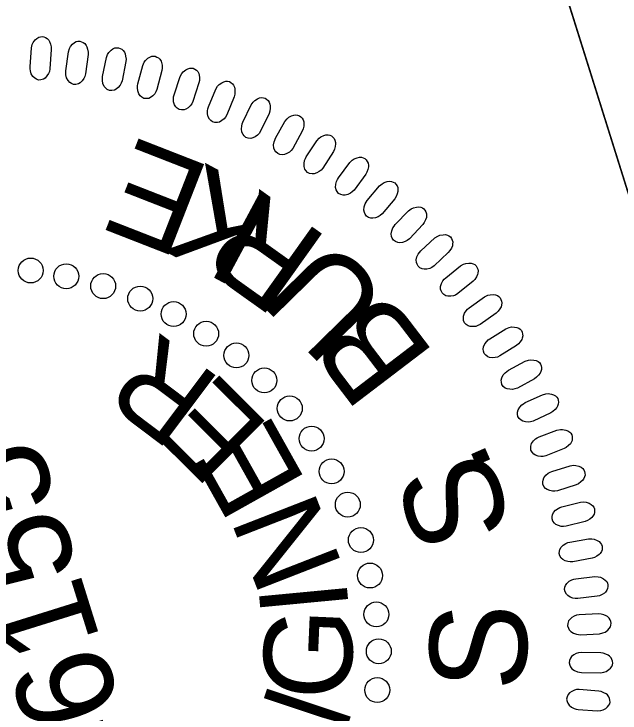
# Model space of a CAD drawing. Extents: x 473667 to 478950, y 494687 to 505998.
# Drawn here: x 473807.69 to 473846.62, y 505639.65 to 505684.57 of the extents above; entities that cross this region are included whole.
import ezdxf

# ---------------------------------------------------------------- set-up
doc = ezdxf.new("R2010")
doc.units = 0
for name, color, linetype in [('Sheet PE Seal Cell', 7, 'Continuous'), ('Sheet Plan CELL', 7, 'Continuous'), ('Sheet Sticker Exception Certification CELL', 7, 'Continuous'), ('Sheet Sticker Incomplete CELL', 7, 'Continuous')]:
    doc.layers.add(name, color=color, linetype=linetype)

msp = doc.modelspace()

# ---------------------------------------------------------------- linework, layer by layer
at = {"layer": 'Sheet PE Seal Cell'}
for points in [[(473808.719, 505681.168), (473808.81, 505682.391), (473808.863, 505682.607), (473808.925, 505682.743), (473809.05, 505682.904), (473809.155, 505683.006), (473809.273, 505683.077), (473809.38, 505683.109), (473809.494, 505683.121), (473809.604, 505683.093), (473809.721, 505683.054), (473809.821, 505682.987), (473809.918, 505682.879), (473809.972, 505682.795), (473810.028, 505682.641), (473810.074, 505682.458), (473810.085, 505682.297), (473809.999, 505681.043), (473809.965, 505680.876), (473809.91, 505680.74), (473809.808, 505680.588), (473809.687, 505680.456), (473809.584, 505680.384), (473809.422, 505680.336), (473809.272, 505680.327), (473809.126, 505680.378), (473809.025, 505680.436), (473808.906, 505680.544), (473808.799, 505680.722), (473808.745, 505680.907), (473808.725, 505681.038)], [(473811.016, 505680.921), (473811.183, 505682.136), (473811.25, 505682.348), (473811.32, 505682.48), (473811.455, 505682.632), (473811.566, 505682.728), (473811.688, 505682.792), (473811.797, 505682.817), (473811.911, 505682.821), (473812.019, 505682.786), (473812.133, 505682.74), (473812.229, 505682.667), (473812.319, 505682.554), (473812.368, 505682.467), (473812.414, 505682.309), (473812.448, 505682.123), (473812.449, 505681.962), (473812.285, 505680.716), (473812.24, 505680.551), (473812.176, 505680.419), (473812.066, 505680.273), (473811.936, 505680.151), (473811.829, 505680.085), (473811.665, 505680.047), (473811.514, 505680.047), (473811.372, 505680.107), (473811.275, 505680.171), (473811.162, 505680.287), (473811.067, 505680.471), (473811.025, 505680.658), (473811.013, 505680.79)], [(473813.379, 505680.562), (473813.622, 505681.765), (473813.702, 505681.972), (473813.781, 505682.099), (473813.924, 505682.243), (473814.042, 505682.331), (473814.167, 505682.387), (473814.278, 505682.406), (473814.391, 505682.403), (473814.498, 505682.361), (473814.609, 505682.308), (473814.699, 505682.229), (473814.782, 505682.11), (473814.825, 505682.02), (473814.861, 505681.86), (473814.884, 505681.672), (473814.875, 505681.512), (473814.634, 505680.278), (473814.578, 505680.117), (473814.506, 505679.988), (473814.387, 505679.85), (473814.249, 505679.735), (473814.138, 505679.677), (473813.973, 505679.649), (473813.821, 505679.659), (473813.683, 505679.728), (473813.591, 505679.798), (473813.485, 505679.92), (473813.402, 505680.109), (473813.372, 505680.3), (473813.368, 505680.432)], [(473815.639, 505680.079), (473815.956, 505681.264), (473816.05, 505681.466), (473816.136, 505681.587), (473816.288, 505681.722), (473816.411, 505681.803), (473816.54, 505681.851), (473816.651, 505681.862), (473816.765, 505681.852), (473816.867, 505681.804), (473816.976, 505681.744), (473817.061, 505681.659), (473817.136, 505681.536), (473817.174, 505681.443), (473817.199, 505681.281), (473817.211, 505681.092), (473817.192, 505680.932), (473816.872, 505679.716), (473816.807, 505679.559), (473816.727, 505679.436), (473816.6, 505679.305), (473816.455, 505679.199), (473816.341, 505679.147), (473816.173, 505679.13), (473816.023, 505679.15), (473815.89, 505679.227), (473815.802, 505679.302), (473815.704, 505679.431), (473815.633, 505679.626), (473815.614, 505679.817), (473815.619, 505679.95)], [(473817.969, 505679.383), (473818.361, 505680.545), (473818.466, 505680.741), (473818.56, 505680.857), (473818.721, 505680.982), (473818.848, 505681.055), (473818.98, 505681.095), (473819.091, 505681.099), (473819.204, 505681.082), (473819.304, 505681.027), (473819.408, 505680.961), (473819.488, 505680.871), (473819.554, 505680.743), (473819.586, 505680.648), (473819.602, 505680.485), (473819.602, 505680.295), (473819.572, 505680.137), (473819.178, 505678.944), (473819.102, 505678.791), (473819.015, 505678.673), (473818.88, 505678.55), (473818.729, 505678.453), (473818.611, 505678.409), (473818.443, 505678.402), (473818.295, 505678.432), (473818.166, 505678.517), (473818.083, 505678.597), (473817.994, 505678.732), (473817.935, 505678.931), (473817.929, 505679.123), (473817.942, 505679.255)], [(473820.184, 505678.605), (473820.648, 505679.74), (473820.765, 505679.929), (473820.865, 505680.039), (473821.034, 505680.154), (473821.166, 505680.218), (473821.3, 505680.25), (473821.411, 505680.247), (473821.523, 505680.222), (473821.618, 505680.162), (473821.718, 505680.089), (473821.792, 505679.994), (473821.852, 505679.862), (473821.877, 505679.765), (473821.882, 505679.602), (473821.87, 505679.413), (473821.83, 505679.257), (473821.362, 505678.09), (473821.277, 505677.942), (473821.182, 505677.83), (473821.04, 505677.716), (473820.883, 505677.629), (473820.762, 505677.592), (473820.594, 505677.596), (473820.449, 505677.635), (473820.326, 505677.728), (473820.248, 505677.814), (473820.168, 505677.954), (473820.121, 505678.156), (473820.126, 505678.348), (473820.148, 505678.479)], [(473822.388, 505677.625), (473822.923, 505678.729), (473823.052, 505678.91), (473823.16, 505679.013), (473823.335, 505679.117), (473823.47, 505679.173), (473823.606, 505679.196), (473823.717, 505679.186), (473823.827, 505679.155), (473823.919, 505679.089), (473824.013, 505679.009), (473824.082, 505678.911), (473824.132, 505678.775), (473824.152, 505678.677), (473824.147, 505678.513), (473824.123, 505678.325), (473824.073, 505678.172), (473823.533, 505677.038), (473823.439, 505676.895), (473823.337, 505676.789), (473823.187, 505676.684), (473823.026, 505676.607), (473822.903, 505676.578), (473822.736, 505676.592), (473822.592, 505676.64), (473822.475, 505676.741), (473822.403, 505676.832), (473822.332, 505676.976), (473822.299, 505677.181), (473822.316, 505677.372), (473822.345, 505677.502)], [(473824.486, 505676.593), (473825.089, 505677.661), (473825.23, 505677.834), (473825.344, 505677.93), (473825.525, 505678.023), (473825.663, 505678.071), (473825.8, 505678.085), (473825.911, 505678.068), (473826.019, 505678.03), (473826.106, 505677.958), (473826.196, 505677.873), (473826.258, 505677.77), (473826.3, 505677.631), (473826.313, 505677.532), (473826.298, 505677.369), (473826.262, 505677.183), (473826.203, 505677.033), (473825.592, 505675.935), (473825.489, 505675.798), (473825.381, 505675.699), (473825.225, 505675.604), (473825.059, 505675.537), (473824.935, 505675.516), (473824.769, 505675.54), (473824.629, 505675.597), (473824.518, 505675.705), (473824.452, 505675.8), (473824.39, 505675.949), (473824.369, 505676.155), (473824.398, 505676.345), (473824.436, 505676.472)], [(473826.464, 505675.396), (473827.133, 505676.425), (473827.283, 505676.589), (473827.403, 505676.677), (473827.59, 505676.759), (473827.731, 505676.798), (473827.869, 505676.803), (473827.978, 505676.78), (473828.083, 505676.735), (473828.165, 505676.658), (473828.25, 505676.567), (473828.305, 505676.46), (473828.338, 505676.319), (473828.345, 505676.22), (473828.32, 505676.058), (473828.272, 505675.874), (473828.204, 505675.729), (473827.526, 505674.671), (473827.414, 505674.541), (473827.3, 505674.449), (473827.139, 505674.364), (473826.969, 505674.308), (473826.843, 505674.294), (473826.68, 505674.329), (473826.543, 505674.394), (473826.44, 505674.509), (473826.379, 505674.608), (473826.326, 505674.761), (473826.319, 505674.968), (473826.36, 505675.156), (473826.406, 505675.28)], [(473828.528, 505674.046), (473829.26, 505675.03), (473829.421, 505675.183), (473829.545, 505675.265), (473829.737, 505675.334), (473829.881, 505675.364), (473830.018, 505675.361), (473830.126, 505675.331), (473830.228, 505675.279), (473830.305, 505675.197), (473830.384, 505675.101), (473830.433, 505674.992), (473830.456, 505674.848), (473830.457, 505674.749), (473830.422, 505674.588), (473830.363, 505674.409), (473830.286, 505674.267), (473829.542, 505673.254), (473829.423, 505673.132), (473829.303, 505673.047), (473829.136, 505672.972), (473828.963, 505672.926), (473828.837, 505672.921), (473828.676, 505672.966), (473828.544, 505673.04), (473828.448, 505673.161), (473828.393, 505673.263), (473828.351, 505673.419), (473828.356, 505673.626), (473828.409, 505673.811), (473828.462, 505673.932)], [(473830.377, 505672.587), (473831.169, 505673.524), (473831.339, 505673.667), (473831.469, 505673.741), (473831.664, 505673.798), (473831.809, 505673.819), (473831.947, 505673.807), (473832.052, 505673.771), (473832.151, 505673.713), (473832.223, 505673.625), (473832.296, 505673.525), (473832.337, 505673.412), (473832.352, 505673.268), (473832.347, 505673.169), (473832.301, 505673.011), (473832.231, 505672.835), (473832.145, 505672.699), (473831.339, 505671.735), (473831.213, 505671.62), (473831.088, 505671.542), (473830.917, 505671.478), (473830.741, 505671.444), (473830.615, 505671.446), (473830.456, 505671.501), (473830.329, 505671.583), (473830.241, 505671.71), (473830.194, 505671.816), (473830.16, 505671.974), (473830.179, 505672.18), (473830.244, 505672.361), (473830.305, 505672.479)], [(473832.178, 505671.036), (473833.029, 505671.922), (473833.207, 505672.054), (473833.342, 505672.119), (473833.54, 505672.164), (473833.686, 505672.175), (473833.822, 505672.155), (473833.925, 505672.111), (473834.02, 505672.048), (473834.087, 505671.956), (473834.152, 505671.852), (473834.187, 505671.736), (473834.193, 505671.592), (473834.181, 505671.493), (473834.126, 505671.338), (473834.045, 505671.167), (473833.95, 505671.037), (473833.086, 505670.125), (473832.952, 505670.018), (473832.822, 505669.948), (473832.648, 505669.895), (473832.471, 505669.872), (473832.345, 505669.882), (473832.19, 505669.947), (473832.068, 505670.037), (473831.989, 505670.169), (473831.947, 505670.278), (473831.924, 505670.437), (473831.956, 505670.642), (473832.032, 505670.819), (473832.1, 505670.933)], [(473833.822, 505669.349), (473834.726, 505670.179), (473834.912, 505670.299), (473835.05, 505670.356), (473835.251, 505670.388), (473835.398, 505670.391), (473835.532, 505670.362), (473835.633, 505670.312), (473835.723, 505670.242), (473835.784, 505670.147), (473835.843, 505670.038), (473835.87, 505669.921), (473835.867, 505669.776), (473835.849, 505669.678), (473835.785, 505669.528), (473835.692, 505669.362), (473835.59, 505669.237), (473834.67, 505668.382), (473834.53, 505668.284), (473834.396, 505668.222), (473834.219, 505668.181), (473834.04, 505668.169), (473833.915, 505668.186), (473833.765, 505668.261), (473833.649, 505668.358), (473833.578, 505668.495), (473833.544, 505668.606), (473833.53, 505668.766), (473833.575, 505668.969), (473833.662, 505669.141), (473833.737, 505669.25)], [(473835.419, 505667.619), (473836.373, 505668.391), (473836.567, 505668.499), (473836.708, 505668.547), (473836.911, 505668.567), (473837.057, 505668.56), (473837.19, 505668.523), (473837.287, 505668.467), (473837.373, 505668.392), (473837.427, 505668.292), (473837.479, 505668.181), (473837.499, 505668.062), (473837.487, 505667.918), (473837.463, 505667.821), (473837.389, 505667.674), (473837.287, 505667.515), (473837.177, 505667.397), (473836.205, 505666.601), (473836.059, 505666.512), (473835.922, 505666.459), (473835.742, 505666.428), (473835.563, 505666.428), (473835.439, 505666.453), (473835.294, 505666.537), (473835.184, 505666.642), (473835.121, 505666.782), (473835.095, 505666.896), (473835.092, 505667.057), (473835.149, 505667.256), (473835.246, 505667.422), (473835.328, 505667.526)], [(473836.924, 505665.689), (473837.924, 505666.399), (473838.125, 505666.495), (473838.269, 505666.534), (473838.472, 505666.541), (473838.618, 505666.525), (473838.748, 505666.479), (473838.841, 505666.417), (473838.922, 505666.336), (473838.97, 505666.234), (473839.015, 505666.12), (473839.027, 505666), (473839.006, 505665.857), (473838.976, 505665.761), (473838.893, 505665.62), (473838.781, 505665.467), (473838.664, 505665.356), (473837.644, 505664.623), (473837.493, 505664.543), (473837.353, 505664.499), (473837.171, 505664.48), (473836.993, 505664.49), (473836.871, 505664.524), (473836.731, 505664.617), (473836.628, 505664.727), (473836.575, 505664.872), (473836.555, 505664.987), (473836.562, 505665.148), (473836.631, 505665.343), (473836.739, 505665.502), (473836.827, 505665.602)], [(473838.25, 505663.702), (473839.293, 505664.348), (473839.499, 505664.432), (473839.645, 505664.461), (473839.849, 505664.455), (473839.993, 505664.431), (473840.12, 505664.377), (473840.209, 505664.309), (473840.285, 505664.224), (473840.327, 505664.119), (473840.364, 505664.001), (473840.369, 505663.881), (473840.339, 505663.739), (473840.303, 505663.647), (473840.211, 505663.51), (473840.09, 505663.365), (473839.966, 505663.262), (473838.902, 505662.594), (473838.746, 505662.523), (473838.604, 505662.488), (473838.42, 505662.48), (473838.243, 505662.502), (473838.124, 505662.543), (473837.991, 505662.644), (473837.894, 505662.762), (473837.85, 505662.91), (473837.837, 505663.025), (473837.854, 505663.185), (473837.936, 505663.376), (473838.053, 505663.528), (473838.148, 505663.622)], [(473839.446, 505661.682), (473840.529, 505662.261), (473840.739, 505662.332), (473840.887, 505662.352), (473841.089, 505662.333), (473841.232, 505662.299), (473841.356, 505662.238), (473841.44, 505662.165), (473841.51, 505662.074), (473841.545, 505661.967), (473841.576, 505661.847), (473841.572, 505661.726), (473841.534, 505661.587), (473841.492, 505661.497), (473841.391, 505661.367), (473841.262, 505661.229), (473841.132, 505661.134), (473840.028, 505660.534), (473839.868, 505660.474), (473839.723, 505660.448), (473839.541, 505660.452), (473839.365, 505660.484), (473839.248, 505660.532), (473839.121, 505660.642), (473839.033, 505660.765), (473838.998, 505660.915), (473838.992, 505661.031), (473839.02, 505661.191), (473839.113, 505661.376), (473839.24, 505661.52), (473839.339, 505661.607)], [(473840.531, 505659.595), (473841.646, 505660.105), (473841.861, 505660.163), (473842.01, 505660.174), (473842.211, 505660.142), (473842.351, 505660.099), (473842.47, 505660.031), (473842.55, 505659.952), (473842.615, 505659.858), (473842.643, 505659.748), (473842.666, 505659.627), (473842.655, 505659.507), (473842.608, 505659.37), (473842.56, 505659.283), (473842.452, 505659.159), (473842.314, 505659.03), (473842.178, 505658.943), (473841.038, 505658.414), (473840.875, 505658.364), (473840.729, 505658.347), (473840.547, 505658.362), (473840.374, 505658.405), (473840.26, 505658.461), (473840.14, 505658.579), (473840.06, 505658.707), (473840.034, 505658.859), (473840.036, 505658.975), (473840.074, 505659.132), (473840.178, 505659.31), (473840.314, 505659.447), (473840.419, 505659.528)], [(473841.423, 505657.396), (473842.569, 505657.835), (473842.786, 505657.879), (473842.935, 505657.88), (473843.134, 505657.836), (473843.271, 505657.785), (473843.386, 505657.708), (473843.46, 505657.625), (473843.519, 505657.527), (473843.54, 505657.416), (473843.555, 505657.293), (473843.537, 505657.174), (473843.481, 505657.04), (473843.428, 505656.956), (473843.313, 505656.84), (473843.166, 505656.72), (473843.025, 505656.642), (473841.855, 505656.185), (473841.689, 505656.145), (473841.542, 505656.137), (473841.361, 505656.164), (473841.19, 505656.218), (473841.081, 505656.281), (473840.969, 505656.406), (473840.897, 505656.539), (473840.881, 505656.692), (473840.89, 505656.808), (473840.937, 505656.962), (473841.053, 505657.134), (473841.197, 505657.262), (473841.307, 505657.336)], [(473842.247, 505655.174), (473843.418, 505655.54), (473843.638, 505655.57), (473843.788, 505655.562), (473843.983, 505655.505), (473844.117, 505655.445), (473844.226, 505655.362), (473844.295, 505655.275), (473844.348, 505655.173), (473844.362, 505655.06), (473844.37, 505654.937), (473844.344, 505654.819), (473844.28, 505654.689), (473844.221, 505654.609), (473844.099, 505654.5), (473843.945, 505654.389), (473843.8, 505654.32), (473842.603, 505653.938), (473842.435, 505653.909), (473842.288, 505653.91), (473842.108, 505653.947), (473841.942, 505654.013), (473841.836, 505654.082), (473841.733, 505654.214), (473841.669, 505654.351), (473841.662, 505654.505), (473841.679, 505654.62), (473841.735, 505654.771), (473841.862, 505654.935), (473842.014, 505655.054), (473842.128, 505655.12)], [(473842.882, 505652.907), (473844.074, 505653.198), (473844.295, 505653.215), (473844.444, 505653.197), (473844.635, 505653.129), (473844.765, 505653.061), (473844.869, 505652.971), (473844.933, 505652.879), (473844.979, 505652.773), (473844.986, 505652.661), (473844.985, 505652.538), (473844.952, 505652.422), (473844.88, 505652.296), (473844.817, 505652.219), (473844.688, 505652.118), (473844.528, 505652.017), (473844.378, 505651.957), (473843.159, 505651.651), (473842.99, 505651.632), (473842.843, 505651.643), (473842.667, 505651.692), (473842.504, 505651.767), (473842.404, 505651.843), (473842.308, 505651.981), (473842.254, 505652.122), (473842.257, 505652.277), (473842.28, 505652.389), (473842.346, 505652.537), (473842.483, 505652.693), (473842.642, 505652.802), (473842.76, 505652.861)], [(473843.386, 505650.636), (473844.594, 505650.853), (473844.816, 505650.855), (473844.963, 505650.828), (473845.15, 505650.748), (473845.275, 505650.671), (473845.374, 505650.575), (473845.431, 505650.479), (473845.47, 505650.372), (473845.47, 505650.259), (473845.462, 505650.135), (473845.422, 505650.022), (473845.342, 505649.902), (473845.274, 505649.828), (473845.139, 505649.736), (473844.973, 505649.645), (473844.82, 505649.595), (473843.585, 505649.365), (473843.414, 505649.358), (473843.268, 505649.378), (473843.095, 505649.437), (473842.938, 505649.523), (473842.843, 505649.605), (473842.756, 505649.748), (473842.71, 505649.892), (473842.723, 505650.046), (473842.753, 505650.158), (473842.829, 505650.301), (473842.974, 505650.448), (473843.14, 505650.547), (473843.262, 505650.599)], [(473843.783, 505648.281), (473845.002, 505648.421), (473845.223, 505648.409), (473845.369, 505648.374), (473845.55, 505648.281), (473845.67, 505648.197), (473845.762, 505648.095), (473845.814, 505647.996), (473845.846, 505647.887), (473845.839, 505647.774), (473845.823, 505647.651), (473845.776, 505647.54), (473845.688, 505647.425), (473845.616, 505647.356), (473845.475, 505647.272), (473845.303, 505647.192), (473845.148, 505647.152), (473843.9, 505647.001), (473843.729, 505647.003), (473843.585, 505647.032), (473843.417, 505647.103), (473843.265, 505647.198), (473843.174, 505647.285), (473843.097, 505647.434), (473843.061, 505647.581), (473843.083, 505647.734), (473843.121, 505647.844), (473843.204, 505647.981), (473843.36, 505648.119), (473843.53, 505648.207), (473843.655, 505648.251)], [(473844.084, 505644.685), (473845.309, 505644.748), (473845.525, 505644.797), (473845.663, 505644.856), (473845.827, 505644.977), (473845.931, 505645.08), (473846.005, 505645.196), (473846.039, 505645.302), (473846.053, 505645.416), (473846.027, 505645.526), (473845.991, 505645.644), (473845.927, 505645.746), (473845.821, 505645.845), (473845.739, 505645.901), (473845.586, 505645.96), (473845.403, 505646.01), (473845.242, 505646.024), (473843.987, 505645.967), (473843.819, 505645.935), (473843.682, 505645.883), (473843.527, 505645.785), (473843.394, 505645.667), (473843.319, 505645.565), (473843.267, 505645.405), (473843.256, 505645.255), (473843.303, 505645.107), (473843.359, 505645.006), (473843.464, 505644.884), (473843.64, 505644.774), (473843.823, 505644.715), (473843.954, 505644.693)], [(473844.139, 505642.257), (473845.366, 505642.244), (473845.586, 505642.279), (473845.726, 505642.329), (473845.897, 505642.44), (473846.008, 505642.536), (473846.088, 505642.648), (473846.129, 505642.751), (473846.151, 505642.863), (473846.132, 505642.975), (473846.103, 505643.096), (473846.045, 505643.201), (473845.945, 505643.306), (473845.867, 505643.367), (473845.718, 505643.436), (473845.539, 505643.498), (473845.38, 505643.522), (473844.123, 505643.543), (473843.953, 505643.522), (473843.813, 505643.479), (473843.653, 505643.391), (473843.512, 505643.281), (473843.431, 505643.184), (473843.37, 505643.028), (473843.348, 505642.879), (473843.386, 505642.729), (473843.436, 505642.624), (473843.533, 505642.495), (473843.701, 505642.374), (473843.881, 505642.305), (473844.01, 505642.274)], [(473843.938, 505639.88), (473845.162, 505639.789), (473845.384, 505639.81), (473845.527, 505639.852), (473845.704, 505639.952), (473845.821, 505640.04), (473845.908, 505640.147), (473845.956, 505640.248), (473845.984, 505640.359), (473845.972, 505640.471), (473845.951, 505640.593), (473845.9, 505640.702), (473845.807, 505640.813), (473845.733, 505640.879), (473845.588, 505640.957), (473845.414, 505641.03), (473845.256, 505641.064), (473844.004, 505641.164), (473843.833, 505641.155), (473843.691, 505641.119), (473843.525, 505641.042), (473843.377, 505640.941), (473843.29, 505640.849), (473843.219, 505640.697), (473843.188, 505640.549), (473843.217, 505640.398), (473843.26, 505640.29), (473843.349, 505640.155), (473843.51, 505640.024), (473843.684, 505639.943), (473843.811, 505639.904)]]:
    msp.add_lwpolyline(points, close=True, dxfattribs=at)
for centre in [(473808.762, 505668.087), (473811.048, 505667.718), (473813.417, 505667.083), (473815.796, 505666.284), (473817.945, 505665.287), (473820.033, 505664.025), (473821.973, 505662.629), (473823.77, 505661.022), (473825.405, 505659.222), (473826.805, 505657.282), (473828.089, 505655.181), (473829.133, 505653.046), (473829.972, 505650.764), (473830.559, 505648.487), (473830.966, 505645.986), (473831.124, 505643.616), (473831.027, 505641.124)]:
    msp.add_circle(centre, 0.801, dxfattribs=at)
at = {"layer": 'Sheet Plan CELL'}
for points in [[(475144.128, 504543.362), (474142.179, 504229.444), (473753.507, 505469.969), (473896.703, 505514.843), (473836.913, 505705.736), (474695.694, 505974.775)], [(473759.453, 505576.677), (473729.55, 505672.088), (473836.913, 505705.736), (473866.82, 505610.313)]]:
    msp.add_lwpolyline(points, close=True, dxfattribs=at)
at = {"layer": 'Sheet Sticker Exception Certification CELL'}
msp.add_line((473896.703, 505514.843), (473836.901, 505705.732), dxfattribs=at)
msp.add_line((473896.703, 505514.843), (473836.901, 505705.732), dxfattribs=at)

# ---------------------------------------------------------------- texts
at = {"layer": 'Sheet PE Seal Cell'}
for s, height, rotation, p in [('E', 6.236, 158.663, (473820.537, 505674.67)), ('K', 6.236, 151.8174, (473824.775, 505672.429)), ('R', 6.236, 144.5423, (473828.024, 505670.061)), ('U', 6.236, 134.4425, (473832.035, 505666.178)), ('B', 6.236, 127.3256, (473834.806, 505662.624)), ('R', 5.669, 143.0583, (473821.127, 505660.991)), ('E', 5.669, 135.1185, (473824.225, 505658)), ('E', 5.669, 119.2389, (473826.514, 505654.451)), ('46155', 6.2363, 107.3761, (473816.048, 505635.447)), ('.', 6.236, 113.623, (473838.578, 505655.253)), ('S', 6.236, 106.7774, (473839.739, 505651.384)), ('N', 5.669, 111.2991, (473828.841, 505649.052)), ('I', 5.669, 95.4195, (473829.213, 505646.283)), ('S', 6.236, 88.1822, (473840.548, 505641.032)), ('G', 5.669, 87.4797, (473829.283, 505640.407)), ('N', 5.669, 71.6001, (473827.79, 505634.811))]:
    msp.add_text(s, height=height, rotation=rotation, dxfattribs=at).set_placement(p)
at = {"layer": 'Sheet Sticker Incomplete CELL'}
for s, height, p in [('INCOMPLETE PLANS', 11.52, (473821.263, 505528.397)), ('DO NOT USE FOR R/W ACQUISITION', 5.76, (473826.924, 505533.576))]:
    msp.add_text(s, height=height, rotation=107.3948, dxfattribs=at).set_placement(p)

doc.saveas('drawing.dxf')
